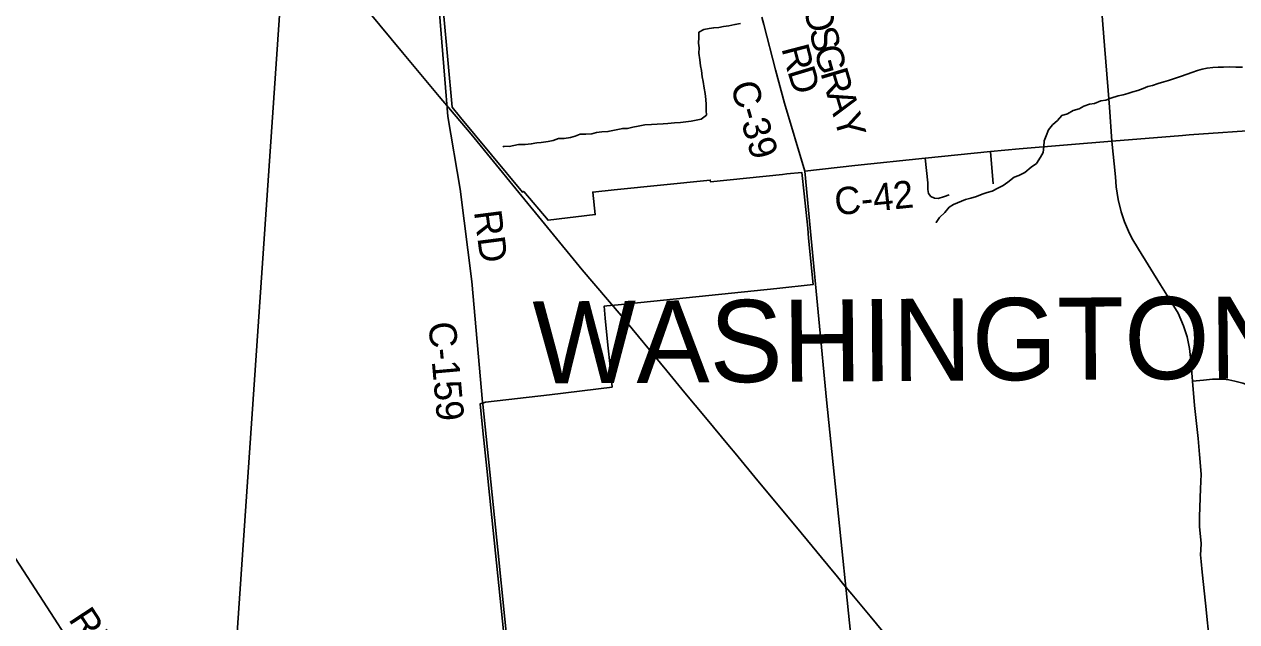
# Model space of a CAD drawing. Extents: x 114604 to 551442, y 316898 to 567001.
# Drawn here: x 145158 to 158450, y 429812 to 436359 of the extents above; entities that cross this region are included whole.
import ezdxf

# ---------------------------------------------------------------- set-up
doc = ezdxf.new("R2010")
doc.units = 0
for name, color, linetype in [('GE_P_Alignment_1000_Bearings', 7, 'Continuous'), ('GE_P_Alignment_1000_Cardinal_Points', 7, 'Continuous'), ('GE_P_Alignment_100_Cardinal_Points', 7, 'Continuous'), ('GE_P_Alignment_100_Stations', 7, 'Continuous'), ('GE_P_Alignment_500_Bearings', 7, 'Continuous'), ('GE_P_Alignment_500_Distances', 7, 'Continuous'), ('GE_P_Alignment_500_Stations', 7, 'Continuous'), ('PM_P_Cells', 7, 'Continuous'), ('PM_P_CL_Double_Solid', 7, 'Continuous'), ('RS_Raster1', 7, 'Continuous')]:
    doc.layers.add(name, color=color, linetype=linetype)

msp = doc.modelspace()

# ---------------------------------------------------------------- linework, layer by layer
at = {"layer": 'GE_P_Alignment_1000_Bearings'}
msp.add_lwpolyline([(154570, 429704), (154430, 429872), (154230, 430114), (154144, 430218), (154057, 430324), (154018, 430370), (153623, 430848), (153199, 431358), (152953, 431658), (152889, 431734), (152628, 432050), (152401, 432322), (152202, 432563), (151700, 433168), (151275, 433667), (150546, 434554), (150058, 435155), (149707, 435567), (149303, 436050), (148169, 437422), (148042, 437573)], dxfattribs=at)
at = {"layer": 'GE_P_Alignment_1000_Cardinal_Points'}
msp.add_line((155778, 434610), (155750, 434964), dxfattribs=at)
msp.add_lwpolyline([(155298, 434489), (155246, 434473), (155178, 434451), (155136, 434454), (155098, 434473), (155071, 434506), (155063, 434550), (155064, 434620), (155036, 434890)], dxfattribs=at)
at = {"layer": 'GE_P_Alignment_100_Cardinal_Points'}
for points in [[(157082, 435079), (157055, 435450), (157040, 435634), (157001, 436127), (156919, 437146), (156883, 437564)], [(157928, 435146), (158771, 435206), (160220, 435341), (160456, 435360), (160922, 435398), (161504, 435447), (161619, 435457), (161671, 435463)], [(153716, 434749), (154263, 434810), (155036, 434890), (155750, 434964), (156064, 434995), (157082, 435079), (157854, 435140), (157928, 435146)], [(158155, 429548), (158106, 430017), (158069, 430354), (158059, 430474), (158054, 430546), (158055, 430600), (158058, 430669), (158051, 430748), (158040, 430854), (158042, 430967), (158054, 431267), (158059, 431429), (158041, 431644), (158026, 431821), (157988, 432183), (157965, 432449), (157946, 432673), (157931, 432805), (157905, 432934), (157867, 433053), (157806, 433193), (157705, 433356), (157613, 433505), (157373, 433894), (157298, 434015), (157263, 434092), (157219, 434193), (157183, 434305), (157151, 434440), (157128, 434576), (157121, 434686), (157082, 435079)], [(157965, 432449), (158086, 432459), (158184, 432470), (158255, 432470), (158301, 432469), (158362, 432464), (158427, 432449), (158515, 432427), (158603, 432395), (158736, 432329), (158821, 432262), (158879, 432210), (158886, 432202)]]:
    msp.add_lwpolyline(points, dxfattribs=at)
at = {"layer": 'GE_P_Alignment_100_Stations'}
msp.add_lwpolyline([(150452, 429321), (150259, 431203), (150230, 431490), (150187, 431904), (150157, 432201), (150215, 432217), (150915, 432300), (151603, 432383), (151581, 432609), (151557, 432841), (151528, 433139), (151515, 433269), (151546, 433272), (151668, 433283), (153407, 433464), (153807, 433508), (153757, 434016), (153747, 434126), (153709, 434502), (153682, 434735), (153517, 434719), (153470, 434714), (152681, 434633), (152679, 434651), (151624, 434544), (151391, 434520), (151417, 434274), (150901, 434211), (150633, 434528), (150622, 434519), (149940, 435339), (149848, 435450), (149755, 436487)], dxfattribs=at)
at = {"layer": 'GE_P_Alignment_500_Bearings'}
for points in [[(150183, 432219), (150065, 433541), (149938, 434551), (149800, 435349), (149768, 435758), (149550, 438468), (149481, 439320)], [(146567, 428190), (146545, 428225), (146526, 428251), (146331, 428554), (145936, 429157), (145721, 429491), (145366, 430037), (145064, 430505), (144797, 430918), (144567, 431276), (144032, 432101), (143429, 433037), (143149, 433468), (142166, 434991), (142073, 435132), (141863, 435459), (141131, 436585), (140458, 437632), (140407, 437716), (140358, 437803)], [(154338, 428524), (153953, 432244), (153783, 434012), (153716, 434749), (153493, 435495), (153393, 435859), (153264, 436358), (153244, 436435)], [(150596, 428008), (150502, 429081), (150348, 430601), (150185, 432198), (150183, 432219)]]:
    msp.add_lwpolyline(points, dxfattribs=at)
at = {"layer": 'GE_P_Alignment_500_Distances'}
for points in [[(147386, 428151), (148148, 439230), (148177, 439983), (151138, 439882), (152473, 439858), (155550, 439725), (156053, 439712), (156142, 439709), (156715, 439694), (157545, 439673), (158384, 439650), (158384, 439701), (158353, 446272), (158350, 446686), (158334, 448459), (158404, 452871)], [(140707, 440166), (147260, 440014), (148177, 439983), (148148, 439230), (147386, 428151)]]:
    msp.add_lwpolyline(points, dxfattribs=at)
at = {"layer": 'PM_P_Cells'}
for points in [[(153009, 436369), (152949, 436355), (152881, 436341), (152825, 436334), (152773, 436324), (152717, 436320), (152665, 436311), (152607, 436301), (152553, 436273)], [(152553, 436273), (152553, 436213), (152548, 436151), (152556, 436099), (152554, 436041), (152563, 435970), (152573, 435902), (152584, 435852), (152590, 435784), (152600, 435730), (152611, 435657), (152621, 435601), (152631, 435533), (152632, 435479), (152634, 435415), (152638, 435364), (152579, 435319), (152523, 435307), (152469, 435297), (152409, 435288), (152351, 435284), (152287, 435280), (152215, 435271), (152163, 435269), (152095, 435264), (152035, 435260), (151963, 435256), (151889, 435243), (151831, 435233), (151771, 435218), (151719, 435218), (151557, 435183), (151491, 435179), (151433, 435174), (151380, 435160), (151316, 435154), (151252, 435153), (151196, 435133), (151146, 435119), (151078, 435108), (151016, 435108), (150958, 435086), (150900, 435073), (150826, 435065), (150776, 435059), (150716, 435048), (150648, 435042), (150578, 435043), (150524, 435031), (150474, 435021), (150416, 435022), (150408, 435012)], [(158511, 435889), (158441, 435887), (158375, 435892), (158305, 435888), (158247, 435889), (158187, 435885), (158125, 435879), (158071, 435866), (158019, 435852), (157959, 435832), (157844, 435789), (157768, 435763), (157700, 435742), (157650, 435728), (157588, 435708), (157528, 435687), (157476, 435677), (157424, 435655), (157366, 435633), (157309, 435618), (157255, 435602), (157203, 435586), (157149, 435575), (157071, 435549), (157015, 435529), (156959, 435520), (156891, 435492), (156837, 435482), (156773, 435463), (156722, 435433), (156658, 435413), (156596, 435377), (156532, 435358), (156484, 435306), (156429, 435256), (156387, 435202), (156361, 435136), (156340, 435082), (156336, 435018), (156326, 434954), (156297, 434902), (156253, 434834), (156195, 434792), (156126, 434735), (156060, 434703), (156010, 434683), (155940, 434630), (155889, 434594), (155831, 434562), (155769, 434530), (155713, 434515), (155659, 434499), (155597, 434471), (155533, 434452)], [(155533, 434452), (155475, 434440), (155346, 434385), (155296, 434353), (155248, 434295), (155191, 434243), (155155, 434187), (155153, 434189)]]:
    msp.add_lwpolyline(points, dxfattribs=at)
at = {"layer": 'RS_Raster1'}
for points in [[(147386, 428151), (148148, 439230), (148177, 439983), (151138, 439882), (152473, 439858), (155550, 439725), (156053, 439712), (156142, 439709), (156715, 439694), (157545, 439673), (158384, 439650), (158384, 439701), (158353, 446272), (158350, 446686), (158334, 448459), (158404, 452871)], [(140707, 440166), (147260, 440014), (148177, 439983), (148148, 439230), (147386, 428151)]]:
    msp.add_lwpolyline(points, dxfattribs=at)

# ---------------------------------------------------------------- texts
at = {"layer": 'GE_P_Alignment_500_Stations'}
msp.add_text('WASHINGTON', height=900, rotation=0.412, dxfattribs=at).set_placement((150734, 432421))
at = {"layer": 'PM_P_CL_Double_Solid'}
for s, rotation, p in [('O', 284.0051, (153696, 436549)), ('S', 284.0024, (153760, 436293)), ('R', 284.5108, (153457, 436096)), ('G', 285.5491, (153811, 436088)), ('D', 286.8142, (153522, 435845)), ('R', 286.5843, (153883, 435828)), ('C-39', 286.3574, (152897, 435691)), ('A', 286.5772, (153954, 435592)), ('Y', 286.5754, (154029, 435339)), ('C-42', 5.9188, (154055, 434264)), ('RD', 277.3528, (150088, 434306)), ('C-159', 275.1069, (149588, 433088)), ('RD', 303.2882, (145636, 429840))]:
    msp.add_text(s, height=300, rotation=rotation, dxfattribs=at).set_placement(p)

doc.saveas('drawing.dxf')
